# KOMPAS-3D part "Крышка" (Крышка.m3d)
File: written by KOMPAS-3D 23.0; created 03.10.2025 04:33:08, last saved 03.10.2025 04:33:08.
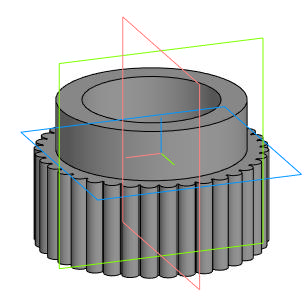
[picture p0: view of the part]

Document properties: Автор: Inspektor_Kot; Полное имя файла: I:\Autodesk Inventor Projects\ИМ-ИТ ЦД\Вариант 14\Крышка.m3d

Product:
- Part/product: Крышка

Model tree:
1. Эскиз:1  (with: Элемент вращения:1)
2. Элемент выдавливания:1  (with: Элемент вращения:1)
     Расстояние 1 = 12
3. Эскиз:2  (with: Элемент выдавливания:1)
4. Элемент выдавливания:2
     Расстояние 1 = 22
5. Эскиз:3  (with: Элемент выдавливания:2)
6. Элемент выдавливания:3  (with: Элемент выдавливания:2)
     Расстояние 1 = -22
7. Массив по концентрической сетке:1  (with: Элемент выдавливания:3, Эскиз:3, Элемент выдавливания:1)  (36 pattern instances)
     Шаг 2 = 360

Referenced files in I:\Autodesk Inventor Projects\ИМ-ИТ ЦД\Вариант 14\: Фонарик.a3d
